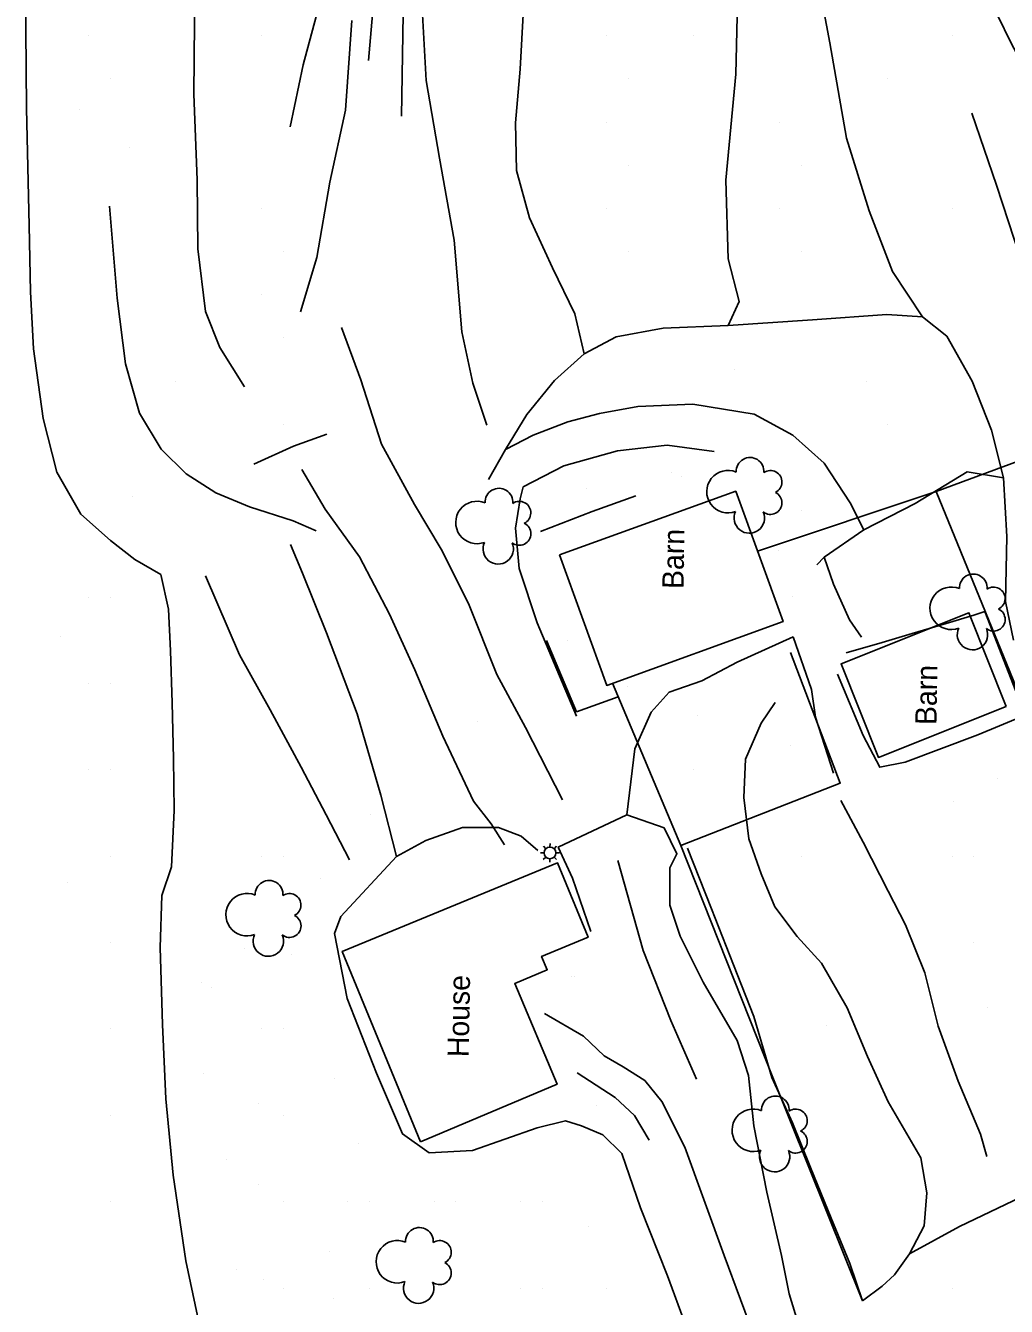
# Model space of a CAD drawing. Extents: x 19528164 to 19545171, y 7585743 to 7602745.
# Drawn here: x 19531890.4 to 19532117.5, y 7588330.8 to 7588627.3 of the extents above; entities that cross this region are included whole.
import ezdxf

# ---------------------------------------------------------------- set-up
doc = ezdxf.new("R2010")
doc.units = 0
for name, color, linetype in [('PhoBreakLine', 7, 'Continuous'), ('PhoBuilding', 7, 'Continuous'), ('PhoDikeDam', 7, 'Continuous'), ('PhoFence', 7, 'Continuous'), ('PhoISAEPoints', 7, 'Continuous'), ('PhoNotesDesign', 7, 'Continuous'), ('PhoVegetation', 7, 'Continuous'), ('SurNaturalCells', 7, 'Continuous'), ('SurROWRail', 7, 'Continuous')]:
    doc.layers.add(name, color=color, linetype=linetype)

msp = doc.modelspace()

# ---------------------------------------------------------------- linework, layer by layer
at = {"layer": 'PhoBreakLine'}
for points in [[(19531924.12, 7588908.45), (19531920.74, 7588891.87), (19531919.36, 7588873.73), (19531919.55, 7588853.92), (19531919.7, 7588835.61), (19531919.8, 7588816.28), (19531920.67, 7588796.84), (19531922.18, 7588778.46), (19531924.37, 7588761.07), (19531926.89, 7588737.23), (19531928.71, 7588720.59), (19531928.97, 7588709.82), (19531928.25, 7588693.49), (19531929.44, 7588667.43), (19531929.87, 7588647.6), (19531929.49, 7588628.02), (19531929.3, 7588611.46), (19531930.06, 7588591.63), (19531930.23, 7588575.68), (19531932.04, 7588561.12), (19531935.35, 7588552.82), (19531941.04, 7588543.7)], [(19531982.48, 7588860.83), (19531991.06, 7588840.83), (19531997.71, 7588816.46), (19532001.45, 7588792.07), (19532004.95, 7588761.99), (19532007.67, 7588740.76), (19532009.47, 7588723.8), (19532009.69, 7588702), (19532009.35, 7588680.86), (19532007.54, 7588660.3), (19532006.11, 7588639.75), (19532004.9, 7588617.25), (19532003.79, 7588604.79), (19532004.04, 7588593.79), (19532007.08, 7588582.86), (19532012.39, 7588571.25), (19532017.58, 7588560.57), (19532019.73, 7588551.35)], [(19531951.61, 7588603.88), (19531954.65, 7588618.24), (19531958.72, 7588633.52), (19531962.99, 7588642.99), (19531966.15, 7588654.67), (19531969.09, 7588670.84), (19531970.01, 7588689.56), (19531970.68, 7588716.4), (19531971.18, 7588738.79), (19531970.93, 7588764.07), (19531970.93, 7588791.34), (19531970.16, 7588811.65), (19531964.73, 7588830.53)], [(19532058.16, 7588702.67), (19532055.59, 7588689.06), (19532055.54, 7588665.95), (19532055.42, 7588639.58), (19532054.88, 7588616.11), (19532052.51, 7588591.53), (19532053.1, 7588573.35), (19532055.62, 7588563.47), (19532053.1, 7588557.9)], [(19532069.81, 7588694.12), (19532070.05, 7588679.97), (19532070.58, 7588666.84), (19532072.45, 7588645.47), (19532076.64, 7588623.34), (19532080.5, 7588601.3), (19532085.7, 7588584.48), (19532091.14, 7588570.43), (19532098.09, 7588559.91)], [(19532096.38, 7588686.82), (19532099.71, 7588672.12), (19532104.43, 7588654.87), (19532112.03, 7588636.79), (19532118.7, 7588623.11), (19532128.48, 7588605), (19532135.37, 7588590.32), (19532142.54, 7588575.49), (19532146.96, 7588564.79), (19532147.32, 7588550.88), (19532144.08, 7588539.85)], [(19531890.35, 7588644.45), (19531890.4, 7588626.49), (19531890.52, 7588608.12), (19531891.21, 7588581.06), (19531891.51, 7588565.67), (19531892.2, 7588552.46), (19531894.41, 7588536.39), (19531897.6, 7588523.94), (19531903.13, 7588514.22), (19531910.03, 7588508.11), (19531915.62, 7588503.7), (19531921.67, 7588500.21), (19531923.45, 7588492.19), (19531923.88, 7588482.57), (19531924.3, 7588470.54), (19531924.61, 7588457.63), (19531924.75, 7588445.57), (19531924.12, 7588432.56), (19531921.94, 7588425.88), (19531921.48, 7588413.84), (19531922.02, 7588396.03), (19531922.8, 7588378.82), (19531924.55, 7588361.17), (19531927.49, 7588341.35), (19531931.21, 7588323.49)], [(19531970.81, 7588631.65), (19531969.77, 7588619.24)], [(19531997.18, 7588534.78), (19531993.95, 7588544.53), (19531991.41, 7588556.42), (19531989.59, 7588577.66), (19531986.21, 7588596.67), (19531983.14, 7588614.63), (19531982.18, 7588631.3)], [(19531965.91, 7588628.53), (19531964.45, 7588607.78), (19531960.78, 7588591.06), (19531957.81, 7588573.62), (19531954, 7588561.04)], [(19532109.52, 7588607.03), (19532115.19, 7588590.42), (19532120.72, 7588573.63), (19532124.47, 7588562.7), (19532130.34, 7588541.61), (19532133.79, 7588529.22), (19532135.99, 7588519.25), (19532139.17, 7588506.2), (19532144.14, 7588492.76), (19532152.92, 7588471.17), (19532163.12, 7588444.26), (19532170.13, 7588426.63), (19532175.48, 7588414.82), (19532180.69, 7588404.74)], [(19531909.78, 7588585.53), (19531911.57, 7588564.25), (19531913.46, 7588548.99), (19531916.72, 7588537.56), (19531921.71, 7588529.22), (19531927.51, 7588523.53), (19531934.38, 7588519.14), (19531942.17, 7588515.92), (19531952.3, 7588512.69), (19531957.61, 7588510.31)], [(19531997.53, 7588522.22), (19532001.51, 7588529.18), (19532006.43, 7588537.26), (19532012.81, 7588545.19), (19532019.73, 7588551.35), (19532027.13, 7588555.24), (19532037.98, 7588557.25), (19532053.1, 7588557.9), (19532072.59, 7588559.18), (19532089.8, 7588560.47), (19532098.09, 7588559.91), (19532103.7, 7588555.45), (19532109.56, 7588544.99), (19532114.04, 7588533.67), (19532116.83, 7588522.64), (19532117.64, 7588509.01), (19532117.28, 7588493.99), (19532119.14, 7588485.06)], [(19531963.55, 7588557.43), (19531968.01, 7588545.31), (19531972.78, 7588530.42), (19531980.45, 7588516.44), (19531986.63, 7588506.09), (19531992.94, 7588493.53), (19531999.48, 7588477.1), (19532006.16, 7588464.8), (19532014.71, 7588448.04)], [(19532001.51, 7588529.18), (19532007.91, 7588532.5), (19532015.9, 7588535.58), (19532023.3, 7588537.53), (19532032.16, 7588539.12), (19532044.89, 7588539.66), (19532059.12, 7588537.38), (19532068.01, 7588532.47), (19532075.32, 7588526.05), (19532081.33, 7588516.8), (19532084.46, 7588510.59)], [(19531960.1, 7588532.74), (19531952.42, 7588529.98), (19531943.22, 7588525.8)], [(19532005.59, 7588520.55), (19532015.03, 7588525.37), (19532027.47, 7588528.87), (19532038.9, 7588530.22), (19532049.83, 7588528.69)], [(19531954.29, 7588524.58), (19531959.74, 7588515.38), (19531967.67, 7588504.31), (19531974.65, 7588491.06), (19531980.52, 7588478.15), (19531987.02, 7588462.8), (19531994.05, 7588447.75), (19531998.15, 7588442.48), (19532001.27, 7588437.62)], [(19532075.3, 7588504.25), (19532084.46, 7588510.59), (19532096.4, 7588516.67), (19532108.43, 7588523.99), (19532116.83, 7588522.64)], [(19532017.95, 7588467.47), (19532008.84, 7588489.05), (19532004.66, 7588501.6), (19532003.83, 7588511), (19532004.87, 7588517.75), (19532005.59, 7588520.55)], [(19532009.57, 7588510.18), (19532021.59, 7588514.82), (19532031.7, 7588518.48)], [(19531976.27, 7588434.91), (19531972.6, 7588449.16), (19531967.13, 7588467.98), (19531960.01, 7588486.72), (19531954.48, 7588500.58), (19531951.68, 7588507.16)], [(19532073.6, 7588502.48), (19532075.3, 7588504.25), (19532077.48, 7588497.99), (19532081.18, 7588489.72), (19532083.97, 7588485.7)], [(19531931.98, 7588499.96), (19531939.9, 7588481.62), (19531946.96, 7588468.9), (19531954.18, 7588455.62), (19531959.93, 7588444.56), (19531965.33, 7588434.15)], [(19532078.41, 7588477.17), (19532084.33, 7588462.92), (19532088.18, 7588455.62), (19532094.08, 7588456.75), (19532110.89, 7588463.13), (19532121.83, 7588467.68), (19532112.51, 7588491.68), (19532109.97, 7588490.85), (19532103.52, 7588488.88), (19532095.71, 7588486.59), (19532088.76, 7588484.49), (19532080.39, 7588482.1)], [(19532029.57, 7588444.61), (19532031.48, 7588459.88), (19532035.27, 7588468.37), (19532039.38, 7588472.96), (19532046.99, 7588475.65), (19532055.15, 7588479.9), (19532068.1, 7588485.82)], [(19532077.48, 7588454.24), (19532073.28, 7588467.18), (19532072.34, 7588473.6), (19532068.1, 7588485.82)], [(19532063.93, 7588470.6), (19532060.68, 7588465.83), (19532057.09, 7588457.46), (19532056.73, 7588448.57), (19532057.85, 7588439.03), (19532060.68, 7588430.94), (19532063.89, 7588423.25), (19532069.02, 7588416.42), (19532074.72, 7588410.28), (19532080.64, 7588399.89), (19532085.35, 7588388.64), (19532090.1, 7588378.1), (19532097.67, 7588365.19), (19532099.06, 7588357.06), (19532098.45, 7588349.42), (19532095.09, 7588342.96), (19532091.59, 7588338.11), (19532088.71, 7588335.48), (19532084.16, 7588332.09)], [(19532079.14, 7588447.87), (19532084.37, 7588438.23), (19532090.14, 7588426.88), (19532094.11, 7588419.11), (19532098.58, 7588407.98), (19532101.73, 7588395.68), (19532106.36, 7588382.94), (19532111.49, 7588370.65), (19532112.94, 7588365.45)], [(19532019.06, 7588372.58), (19532015.4, 7588373.75), (19532008.85, 7588372.14), (19531993.83, 7588366.85), (19531983.78, 7588366.34), (19531977.64, 7588370.7), (19531971.62, 7588384.79), (19531964.8, 7588402.06), (19531961.9, 7588417.08), (19531963.34, 7588421.02), (19531976.27, 7588434.91), (19531983.02, 7588438.68), (19531991.52, 7588441.64), (19531999.91, 7588441.63), (19532005.09, 7588439.62), (19532008.98, 7588436.32)], [(19532084.16, 7588332.09), (19532081.27, 7588340.7), (19532076.89, 7588351.18), (19532072.1, 7588362.9), (19532067.95, 7588373.28), (19532063.21, 7588383.73), (19532059.01, 7588397.86), (19532054.31, 7588409.83), (19532049.2, 7588422.82), (19532043.62, 7588436.89)], [(19532045.77, 7588383.38), (19532039.81, 7588396.94), (19532033.35, 7588413.14), (19532027.48, 7588434.01)], [(19532018.07, 7588384.83), (19532026.93, 7588379.15), (19532031.38, 7588374.94), (19532034.79, 7588369.29)], [(19532043.11, 7588326.73), (19532039, 7588337.82), (19532032.79, 7588353.62), (19532028.44, 7588366.2), (19532024.01, 7588370.51), (19532019.06, 7588372.58)], [(19532095.09, 7588342.96), (19532106.67, 7588349.23), (19532122.65, 7588356.91), (19532138.42, 7588364.98), (19532151.55, 7588372.11)]]:
    msp.add_lwpolyline(points, dxfattribs=at)
at = {"layer": 'PhoBuilding'}
for points in [[(19532014.03, 7588504.77), (19532054.84, 7588519.53), (19532065.77, 7588489.32), (19532024.96, 7588474.56)], [(19532117.49, 7588469.7), (19532087.87, 7588457.88), (19532079.21, 7588479.56), (19532108.84, 7588491.38)], [(19531981.78, 7588368.84), (19531963.68, 7588412.96), (19532013.57, 7588433.44), (19532020.63, 7588416.23), (19532009.86, 7588411.82), (19532011.18, 7588408.73), (19532003.62, 7588405.55), (19532013.46, 7588382.2)]]:
    msp.add_lwpolyline(points, close=True, dxfattribs=at)
at = {"layer": 'PhoDikeDam'}
msp.add_lwpolyline([(19531977.44, 7588606.37), (19531978.51, 7588672.6), (19531980.53, 7588741.9), (19531978.29, 7588792.2), (19531971.81, 7588834.77)], dxfattribs=at)
at = {"layer": 'PhoFence'}
msp.add_line((19532042.13, 7588437.47), (19532026.3, 7588475.04), dxfattribs=at)
for points in [[(19532413.6, 7588629.09), (19532354.85, 7588609.21), (19532285.42, 7588585.45), (19532228.32, 7588563.7), (19532175.6, 7588546.51), (19532137.73, 7588532.93), (19532101.25, 7588519.42), (19532059.87, 7588505.63)], [(19532101.25, 7588519.42), (19532135.52, 7588435.6), (19532160.91, 7588375.73)], [(19532027.62, 7588471.92), (19532017.94, 7588468.47), (19532011, 7588484.95)], [(19532084.16, 7588332.09), (19532063.24, 7588384.12), (19532042.13, 7588437.47), (19532079.02, 7588451.91), (19532067.54, 7588482.19)]]:
    msp.add_lwpolyline(points, dxfattribs=at)
at = {"layer": 'PhoISAEPoints'}
for p, q in [((19531905, 7588625), (19531905, 7588625)), ((19531945, 7588625), (19531945, 7588625)), ((19532025, 7588625), (19532025, 7588625)), ((19532045, 7588625), (19532045, 7588625)), ((19532105, 7588625), (19532105, 7588625)), ((19531910, 7588615), (19531910, 7588615)), ((19531910, 7588615), (19531910, 7588615)), ((19532030, 7588615), (19532030, 7588615)), ((19532030, 7588615), (19532030, 7588615)), ((19532090, 7588615), (19532090, 7588615)), ((19532090, 7588615), (19532090, 7588615)), ((19531902.73, 7588607.96), (19531902.73, 7588607.96)), ((19532025, 7588605), (19532025, 7588605)), ((19532065, 7588605), (19532065, 7588605)), ((19531914.3, 7588599.22), (19531914.3, 7588599.22)), ((19532030, 7588595), (19532030, 7588595)), ((19532030, 7588595), (19532030, 7588595)), ((19532070, 7588595), (19532070, 7588595)), ((19532070, 7588595), (19532070, 7588595)), ((19531945, 7588585), (19531945, 7588585)), ((19532025, 7588585), (19532025, 7588585)), ((19532065, 7588585), (19532065, 7588585)), ((19532105, 7588585), (19532105, 7588585)), ((19531950, 7588575), (19531950, 7588575)), ((19531950, 7588575), (19531950, 7588575)), ((19532030, 7588575), (19532030, 7588575)), ((19532030, 7588575), (19532030, 7588575)), ((19532070, 7588575), (19532070, 7588575)), ((19532070, 7588575), (19532070, 7588575)), ((19531945, 7588565), (19531945, 7588565)), ((19531950, 7588555), (19531950, 7588555)), ((19531950, 7588555), (19531950, 7588555)), ((19532054.56, 7588547.71), (19532054.56, 7588547.71)), ((19531925, 7588545), (19531925, 7588545)), ((19532085, 7588545), (19532085, 7588545)), ((19531950, 7588535), (19531950, 7588535)), ((19531950, 7588535), (19531950, 7588535)), ((19532090, 7588535), (19532090, 7588535)), ((19532090, 7588535), (19532090, 7588535)), ((19532039.91, 7588523.92), (19532039.91, 7588523.92)), ((19532042.18, 7588522.97), (19532042.18, 7588522.97)), ((19532020.34, 7588520.22), (19532020.34, 7588520.22)), ((19531915.21, 7588518.23), (19531915.21, 7588518.23)), ((19532065, 7588515), (19532065, 7588515)), ((19532070, 7588515), (19532070, 7588515)), ((19532064.68, 7588505.76), (19532064.68, 7588505.76)), ((19532067.95, 7588495.23), (19532067.95, 7588495.23)), ((19531905, 7588495), (19531905, 7588495)), ((19531910, 7588495), (19531910, 7588495)), ((19531910, 7588495), (19531910, 7588495)), ((19531898.49, 7588485.88), (19531898.49, 7588485.88)), ((19532015.76, 7588484.99), (19532015.76, 7588484.99)), ((19531905, 7588475), (19531905, 7588475)), ((19531910, 7588475), (19531910, 7588475)), ((19531910, 7588475), (19531910, 7588475)), ((19532029.73, 7588474.25), (19532029.73, 7588474.25)), ((19531995.06, 7588466.27), (19531995.06, 7588466.27)), ((19532045.94, 7588467.68), (19532045.94, 7588467.68)), ((19532067.46, 7588460.68), (19532067.46, 7588460.68)), ((19531905, 7588455), (19531905, 7588455)), ((19531910, 7588455), (19531910, 7588455)), ((19531910, 7588455), (19531910, 7588455)), ((19532045, 7588455), (19532045, 7588455)), ((19532115.39, 7588453.06), (19532115.39, 7588453.06)), ((19531970.12, 7588444.75), (19531970.12, 7588444.75)), ((19532105.28, 7588447.58), (19532105.28, 7588447.58)), ((19531910, 7588435), (19531910, 7588435)), ((19531910, 7588435), (19531910, 7588435)), ((19531945, 7588435), (19531945, 7588435)), ((19531950, 7588435), (19531950, 7588435)), ((19532070, 7588435), (19532070, 7588435)), ((19532105, 7588435), (19532105, 7588435)), ((19532110, 7588435), (19532110, 7588435)), ((19531958.61, 7588429.86), (19531958.61, 7588429.86)), ((19531900, 7588428.94), (19531900, 7588428.94)), ((19531910, 7588415), (19531910, 7588415)), ((19531910, 7588415), (19531910, 7588415)), ((19531941.13, 7588413.64), (19531941.13, 7588413.64)), ((19531951.87, 7588412.21), (19531951.87, 7588412.21)), ((19532110, 7588415), (19532110, 7588415)), ((19532110, 7588415), (19532110, 7588415)), ((19532016.73, 7588407.12), (19532016.73, 7588407.12)), ((19532017.43, 7588407.1), (19532017.43, 7588407.1)), ((19531931.13, 7588405.88), (19531931.13, 7588405.88)), ((19531933.3, 7588404.67), (19531933.3, 7588404.67)), ((19532113.03, 7588400.03), (19532113.03, 7588400.03)), ((19531910, 7588395), (19531910, 7588395)), ((19531910, 7588395), (19531910, 7588395)), ((19531945, 7588395), (19531945, 7588395)), ((19531950, 7588395), (19531950, 7588395)), ((19531950, 7588395), (19531950, 7588395)), ((19532075.78, 7588395.74), (19532075.78, 7588395.74)), ((19531931.65, 7588384.6), (19531931.65, 7588384.6)), ((19531962, 7588383.61), (19531962, 7588383.61)), ((19531944.4, 7588377.67), (19531944.4, 7588377.67)), ((19532022.66, 7588377.21), (19532022.66, 7588377.21)), ((19531910, 7588375), (19531910, 7588375)), ((19531910, 7588375), (19531910, 7588375)), ((19531950, 7588375), (19531950, 7588375)), ((19531950, 7588375), (19531950, 7588375)), ((19531967.42, 7588368.57), (19531967.42, 7588368.57)), ((19531936.77, 7588364.74), (19531936.77, 7588364.74)), ((19531944.36, 7588358.98), (19531944.36, 7588358.98)), ((19531910, 7588355), (19531910, 7588355)), ((19531910, 7588355), (19531910, 7588355)), ((19531950, 7588355), (19531950, 7588355)), ((19531950, 7588355), (19531950, 7588355)), ((19531965, 7588355), (19531965, 7588355)), ((19531970, 7588355), (19531970, 7588355)), ((19531985, 7588355), (19531985, 7588355)), ((19531990, 7588355), (19531990, 7588355)), ((19532005, 7588355), (19532005, 7588355)), ((19532010, 7588355), (19532010, 7588355)), ((19532020.66, 7588349.16), (19532020.66, 7588349.16)), ((19531960.68, 7588343.4), (19531960.68, 7588343.4)), ((19531939.1, 7588339.31), (19531939.1, 7588339.31)), ((19531945.36, 7588336.92), (19531945.36, 7588336.92)), ((19531950, 7588335), (19531950, 7588335)), ((19531950, 7588335), (19531950, 7588335)), ((19531970, 7588335), (19531970, 7588335)), ((19531985, 7588335), (19531985, 7588335)), ((19532005, 7588335), (19532005, 7588335)), ((19532010, 7588335), (19532010, 7588335)), ((19532025, 7588335), (19532025, 7588335)), ((19532105, 7588335), (19532105, 7588335)), ((19531961.62, 7588332.69), (19531961.62, 7588332.69))]:
    msp.add_line(p, q, dxfattribs=at)
at = {"layer": 'PhoVegetation'}
for centre, radius, start, end in [((19532058.13, 7588524.13), 3.21, 355.0513, 183.0549), ((19532053.03, 7588519.42), 4.92, 67.2582, 290.848), ((19532062.84, 7588521.65), 2.67, 295.5773, 124.4564), ((19531999.98, 7588516.99), 3.21, 355.0513, 183.0549), ((19532062.84, 7588516.82), 2.68, 231.8032, 64.3754), ((19531994.88, 7588512.28), 4.92, 67.2582, 290.848), ((19532004.69, 7588514.51), 2.67, 295.5773, 124.4564), ((19532057.96, 7588513.31), 3.52, 154.5355, 23.5706), ((19532004.69, 7588509.68), 2.68, 231.8032, 64.3754), ((19531999.81, 7588506.17), 3.52, 154.5355, 23.5706), ((19532109.83, 7588497.13), 3.21, 355.0513, 183.0549), ((19532104.72, 7588492.42), 4.92, 67.2582, 290.848), ((19532114.54, 7588494.65), 2.67, 295.5773, 124.4564), ((19532114.53, 7588489.83), 2.68, 231.8032, 64.3754), ((19532109.65, 7588486.31), 3.52, 154.5355, 23.5706), ((19531946.75, 7588426.18), 3.21, 355.0513, 183.0549), ((19531941.65, 7588421.47), 4.92, 67.2582, 290.848), ((19531951.46, 7588423.7), 2.67, 295.5773, 124.4564), ((19531951.46, 7588418.87), 2.68, 231.8032, 64.3754), ((19531946.57, 7588415.36), 3.52, 154.5355, 23.5706), ((19532063.99, 7588376.26), 3.21, 355.0513, 183.0549), ((19532058.88, 7588371.55), 4.92, 67.2582, 290.848), ((19532068.7, 7588373.78), 2.67, 295.5773, 124.4564), ((19532068.69, 7588368.95), 2.68, 231.8032, 64.3754), ((19532063.81, 7588365.44), 3.52, 154.5355, 23.5706), ((19531981.56, 7588345.81), 3.21, 355.0513, 183.0549), ((19531976.45, 7588341.1), 4.92, 67.2582, 290.848), ((19531986.26, 7588343.33), 2.67, 295.5773, 124.4564), ((19531986.26, 7588338.5), 2.68, 231.8032, 64.3754), ((19531981.38, 7588334.99), 3.52, 154.5355, 23.5706)]:
    msp.add_arc(centre, radius, start, end, dxfattribs=at)
at = {"layer": 'SurNaturalCells'}
for p, q in [((19532009.62, 7588435.79), (19532010.43, 7588435.79)), ((19532010.84, 7588436.74), (19532010.27, 7588437.32)), ((19532011.8, 7588437.13), (19532011.81, 7588437.95)), ((19532012.76, 7588436.73), (19532013.34, 7588437.3)), ((19532010.24, 7588434.25), (19532010.82, 7588434.82)), ((19532011.77, 7588433.6), (19532011.78, 7588434.41)), ((19532013.31, 7588434.22), (19532012.74, 7588434.8)), ((19532013.15, 7588435.76), (19532013.97, 7588435.76))]:
    msp.add_line(p, q, dxfattribs=at)
msp.add_circle((19532011.79, 7588435.77), 1.36, dxfattribs=at)
at = {"layer": 'SurROWRail'}
for points in [[(19532013.68, 7588437.12), (19532029.57, 7588444.61), (19532038.24, 7588441.59), (19532041.18, 7588435.57), (19532039.57, 7588432.28), (19532039.56, 7588423.65), (19532041.95, 7588416.52), (19532047.24, 7588405.84), (19532055.18, 7588392.34), (19532057.74, 7588384.22), (19532059.04, 7588372.58), (19532062, 7588357.21), (19532065.41, 7588342.54), (19532067.18, 7588333.64), (19532069.41, 7588326.37)], [(19532013.68, 7588437.12), (19532017.04, 7588429.9), (19532021.27, 7588417.54)], [(19532059.69, 7588322.16), (19532052.17, 7588342.55), (19532043.06, 7588367.67), (19532037.67, 7588378.19), (19532033.75, 7588383.1), (19532028.77, 7588386.2), (19532024.38, 7588388.76), (19532019.59, 7588393.34), (19532010.49, 7588398.6)]]:
    msp.add_lwpolyline(points, dxfattribs=at)

# ---------------------------------------------------------------- texts
at = {"layer": 'PhoNotesDesign'}
for s, p in [('Barn', (19532042.71, 7588496.86)), ('Barn', (19532101.3, 7588465.36)), ('House', (19531992.97, 7588388.45))]:
    msp.add_text(s, height=4.92, rotation=89.0083, dxfattribs=at).set_placement(p)

doc.saveas('drawing.dxf')
